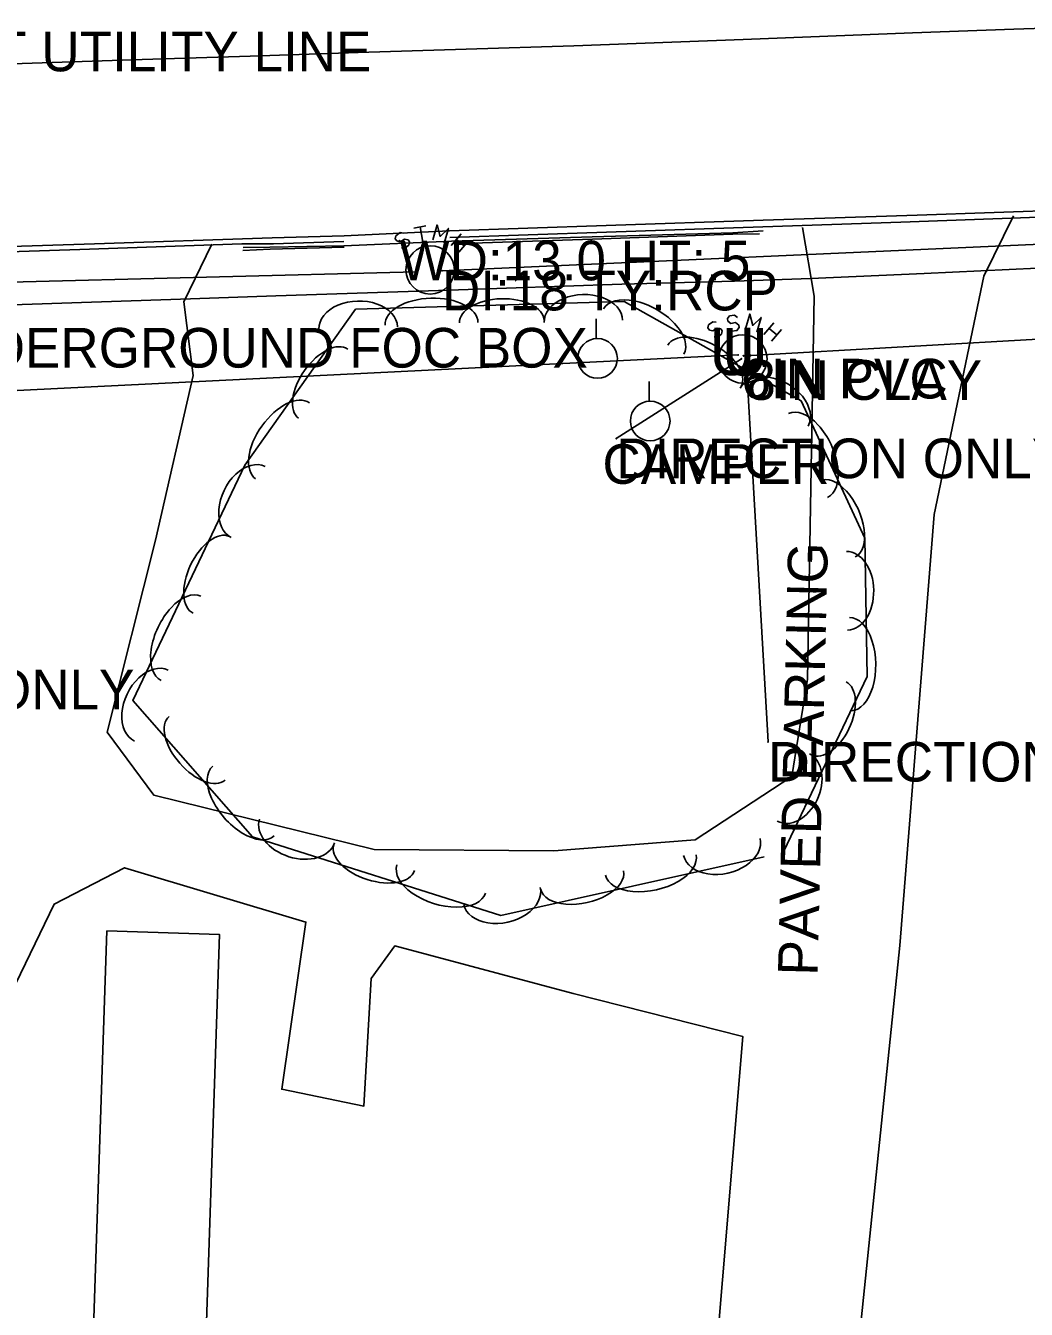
# Model space of a CAD drawing. Extents: x 978516 to 993312, y 1836504 to 1846212.
# Drawn here: x 982988.3 to 983114.4, y 1842518.7 to 1842680.5 of the extents above; entities that cross this region are included whole.
import ezdxf

# ---------------------------------------------------------------- set-up
doc = ezdxf.new("R2010")
doc.units = 0
for name, color, linetype in [('Default', 7, 'Continuous'), ('S_BUILDING', 7, 'Continuous'), ('S_CATCH_BASIN_ANNOT', 7, 'Continuous'), ('S_CURB', 7, 'Continuous'), ('S_DRG_PT_SYM', 7, 'Continuous'), ('S_EDGE_PAVEMENT', 7, 'Continuous'), ('S_ELECTRIC_UTILITIES_ANNOT', 7, 'Continuous'), ('S_MISC_STRUCTURES_ANNOT', 7, 'Continuous'), ('S_PARKING', 7, 'Continuous'), ('S_PARKING_ANNOT', 7, 'Continuous'), ('S_PAVEMENT_CROWN', 7, 'Continuous'), ('S_SANITARY_SEWER', 7, 'Continuous'), ('S_SANITARY_SEWER_ANNOT', 7, 'Continuous'), ('S_SIDEWALK', 7, 'Continuous'), ('S_STORM_SEWER', 7, 'Continuous'), ('S_STORM_SEWER_ANNOT', 7, 'Continuous'), ('S_SURVEY_TEXT_ANNOT', 7, 'Continuous'), ('S_TREE', 7, 'Continuous'), ('S_UNDERGROUND_CABLE', 7, 'Continuous'), ('S_UTILITY_POLE', 7, 'Continuous'), ('S_UTL_PT_SYM', 7, 'Continuous')]:
    doc.layers.add(name, color=color, linetype=linetype)

msp = doc.modelspace()

# ---------------------------------------------------------------- linework, layer by layer
at = {"layer": 'S_BUILDING'}
msp.add_lwpolyline([(982998.5, 1842566.4), (982996.27, 1842500.03), (983010.5, 1842499.55), (983012.72, 1842565.93)], close=True, dxfattribs=at)
at = {"layer": 'S_CURB'}
for points in [[(983041.78, 1842653.78), (983061.51, 1842654.45), (983081.23, 1842655.12), (983098.62, 1842655.72), (983116.01, 1842656.33), (983120.03, 1842656.47), (983141.41, 1842657.25), (983162.79, 1842658.03), (983179.32, 1842658.68), (983195.86, 1842659.33), (983199.41, 1842659.55), (983205.89, 1842659.81)], [(983015.71, 1842652.51), (983019.07, 1842652.56), (983028.41, 1842652.74), (983041.99, 1842653.33), (983059.7, 1842653.85), (983077.42, 1842654.37), (983081.27, 1842654.64)], [(983042.1, 1842652.99), (983059.76, 1842653.58), (983077.42, 1842654.18), (983080.82, 1842654.23)], [(982904.98, 1842649.33), (982922.41, 1842649.89), (982939.84, 1842650.46), (982957.27, 1842651.02), (982974.69, 1842651.59), (982995.11, 1842652.28), (983015.52, 1842652.98), (983019.52, 1842653), (983028.38, 1842653.26)], [(983015.65, 1842652.14), (983019.12, 1842652.31), (983028.44, 1842652.57)]]:
    msp.add_lwpolyline(points, dxfattribs=at)
at = {"layer": 'S_DRG_PT_SYM'}
msp.add_lwpolyline([(983035.43, 1842653.38), (983035.43, 1842653.43), (983035.43, 1842653.38), (983035.38, 1842653.38), (983035.43, 1842653.38), (983035.43, 1842653.33), (983035.43, 1842653.38), (983035.48, 1842653.38)], dxfattribs=at)
at = {"layer": 'S_EDGE_PAVEMENT'}
msp.add_lwpolyline([(982799.93, 1842644.75), (982803.11, 1842645), (982816.92, 1842646.1), (982830.64, 1842646.83), (982844.36, 1842647.55), (982858.08, 1842648.28), (982871.81, 1842649.01), (982891.93, 1842649.67), (982904.86, 1842650.05), (982922.29, 1842650.6), (982939.73, 1842651.16), (982957.17, 1842651.71), (982974.61, 1842652.26), (982996.98, 1842652.99), (983019.36, 1842653.72), (983028.43, 1842653.99), (983041.71, 1842654.6), (983061.49, 1842655.28), (983081.27, 1842655.97), (983100.68, 1842656.61), (983120.09, 1842657.26)], dxfattribs=at)
at = {"layer": 'S_PARKING'}
for points in [[(983077.21, 1842273.31), (983079.69, 1842380.16), (983091.07, 1842492.48), (983098.49, 1842564.53), (983102.83, 1842618.85), (983109.07, 1842648.92), (983112.84, 1842656.52)], [(983086.24, 1842655.06), (983087.68, 1842646.4), (983086.84, 1842598.1), (983084.88, 1842585.84), (983072.67, 1842577.86), (983054.88, 1842576.48), (983032.2, 1842576.64), (983004.43, 1842583.49), (982998.57, 1842591.41), (983004.66, 1842615.62), (983009.41, 1842636.37), (983008.22, 1842645.69), (983011.74, 1842652.92)], [(982984.15, 1842651.53), (982984.99, 1842645.15), (982983.03, 1842614.12), (982974.3, 1842588.15), (982962.33, 1842519.11), (982978.17, 1842519.44), (982985.25, 1842556), (982991.86, 1842569.75), (983000.75, 1842574.33), (983023.62, 1842567.5), (983020.58, 1842546.43), (983030.93, 1842544.29), (983031.86, 1842560.4), (983034.84, 1842564.5), (983057.31, 1842558.5), (983078.68, 1842553.08), (983074.89, 1842507.31), (983067.14, 1842414.68), (983057.78, 1842326.04), (983057.9, 1842278.78)]]:
    msp.add_lwpolyline(points, dxfattribs=at)
at = {"layer": 'S_PAVEMENT_CROWN'}
msp.add_lwpolyline([(982847.58, 1842670.55), (982870.67, 1842671.69), (982893.68, 1842672.48), (982916.68, 1842673.27), (982937.07, 1842674), (982957.45, 1842674.72), (982980.22, 1842675.47), (983002.98, 1842676.22), (983016.59, 1842676.65), (983030.19, 1842677.08), (983043.8, 1842677.51), (983057.4, 1842677.94), (983078.75, 1842678.75), (983100.11, 1842679.56), (983112.88, 1842680.02), (983125.65, 1842680.48)], dxfattribs=at)
at = {"layer": 'S_SANITARY_SEWER'}
for p, q in [((983074.38, 1842642.78), (983074.3, 1842642.39)), ((983074.3, 1842642.39), (983074.5, 1842642.12)), ((983074.92, 1842643.17), (983074.38, 1842642.78)), ((983074.5, 1842642.12), (983074.92, 1842642)), ((983075.35, 1842643.09), (983074.92, 1842643.17)), ((983074.92, 1842642), (983075.47, 1842642.35)), ((983075.47, 1842642.35), (983075.93, 1842642.27)), ((983075.93, 1842642.27), (983076.09, 1842642)), ((983076.09, 1842642), (983076.01, 1842641.58)), ((983081.36, 1842641.54), (983082.6, 1842643.01)), ((983082.01, 1842642.31), (983082.98, 1842641.5)), ((983083.56, 1842642.2), (983082.32, 1842640.72)), ((983075.47, 1842641.19), (983075.08, 1842641.27)), ((983076.01, 1842641.58), (983075.47, 1842641.19)), ((983078.52, 1842638.49), (983062.75, 1842628.44)), ((983079.14, 1842638.31), (983081.88, 1842590.2))]:
    msp.add_line(p, q, dxfattribs=at)
for points in [[(983078.02, 1842643.71), (983077.67, 1842643.98), (983077.02, 1842643.9), (983076.78, 1842643.55), (983076.82, 1842643.24), (983077.17, 1842642.93), (983077.79, 1842643.05), (983078.18, 1842642.74), (983078.22, 1842642.43), (983077.95, 1842642.04), (983077.33, 1842641.96), (983076.98, 1842642.24)], [(983080.46, 1842641.85), (983081.01, 1842643.71), (983079.96, 1842642.7), (983079.57, 1842644.13), (983079.03, 1842642.27)]]:
    msp.add_lwpolyline(points, dxfattribs=at)
msp.add_circle((983078.71, 1842638.47), 3.05, dxfattribs=at)
at = {"layer": 'S_SIDEWALK'}
msp.add_lwpolyline([(982810.26, 1842638.37), (982817.4, 1842638.97), (982827.62, 1842639.18), (982840.18, 1842639.82), (982852.74, 1842640.46), (982865.3, 1842641.1), (982877.86, 1842641.74), (982891.92, 1842642.24), (982905.28, 1842642.67), (982922.7, 1842643.24), (982940.13, 1842643.81), (982957.56, 1842644.38), (982974.98, 1842644.95), (982985.37, 1842645.26), (983009.07, 1842646.03), (983019.82, 1842646.43), (983041.63, 1842647.16), (983063.45, 1842647.9), (983077.67, 1842648.27), (983087.26, 1842648.6), (983101.56, 1842649.26), (983115.86, 1842649.93)], dxfattribs=at)
at = {"layer": 'S_STORM_SEWER'}
for p, q in [((983037.24, 1842654.97), (983038.75, 1842655.24)), ((983038.01, 1842655.12), (983038.36, 1842653.19)), ((983034.95, 1842654), (983034.88, 1842653.61)), ((983034.88, 1842653.61), (983035.07, 1842653.34)), ((983035.5, 1842654.39), (983034.95, 1842654)), ((983035.07, 1842653.34), (983035.5, 1842653.22)), ((983035.92, 1842654.31), (983035.5, 1842654.39)), ((983035.5, 1842653.22), (983036.04, 1842653.57)), ((983036.04, 1842653.57), (983036.5, 1842653.5)), ((983036.5, 1842653.5), (983036.66, 1842653.22)), ((983040.77, 1842649.59), (983148.86, 1842654.38)), ((983041.93, 1842652.76), (983043.17, 1842654.23)), ((983042.59, 1842653.53), (983043.56, 1842652.72)), ((983044.14, 1842653.42), (983042.9, 1842651.95)), ((983036.04, 1842652.41), (983035.65, 1842652.49)), ((983036.58, 1842652.8), (983036.04, 1842652.41)), ((983036.66, 1842653.22), (983036.58, 1842652.8)), ((982904.36, 1842646.08), (983037.51, 1842649.46))]:
    msp.add_line(p, q, dxfattribs=at)
msp.add_lwpolyline([(983041.04, 1842653.07), (983041.58, 1842654.93), (983040.53, 1842653.92), (983040.15, 1842655.36), (983039.6, 1842653.5)], dxfattribs=at)
msp.add_circle((983039.28, 1842649.7), 3.05, dxfattribs=at)
at = {"layer": 'S_TREE'}
msp.add_lwpolyline([(983081.41, 1842575.72), (983048.18, 1842568.31), (983016.88, 1842578.25), (983001.8, 1842595.4), (983015.91, 1842625.07), (983029.87, 1842644.76), (983063.74, 1842645.73), (983086.04, 1842633.21), (983094.09, 1842615.88), (983094.38, 1842598.43), (983083.86, 1842576.44)], dxfattribs=at)
for centre, major_axis, ratio, start_param, end_param in [((983030.21, 1842642.38), (-4.95, -0.15), 0.685874, 3.140501, 6.282094), ((983039.45, 1842642.91), (-5.86, -0.17), 0.550532, 3.140927, 6.282519), ((983048.3, 1842643.17), (-5.34, -0.16), 0.541144, 3.140948, 6.28254), ((983058.6, 1842643.2), (-4.95, -0.15), 0.685874, 3.140501, 6.282094), ((983066.21, 1842641.92), (-5.06, 2.86), 0.554687, 3.145722, 6.287315), ((983073.87, 1842637.61), (-4.61, 2.6), 0.545228, 3.145592, 6.287184), ((983025.79, 1842635.35), (-3.08, -4.36), 0.539235, 3.137057, 6.278649), ((983082.64, 1842632.39), (-4.27, 2.42), 0.691042, 3.14841, 6.290003), ((983020.67, 1842628.14), (-3.38, -4.79), 0.54859, 3.136911, 6.278503), ((983086.92, 1842626.3), (-2.43, 5.3), 0.551823, 3.150215, 6.291808), ((983016.34, 1842620.45), (-2.12, -4.48), 0.68184, 3.138691, 6.280284), ((983090.63, 1842618.32), (-2.21, 4.82), 0.542415, 3.149944, 6.291537), ((983011.68, 1842611.26), (-2.29, -4.83), 0.537963, 3.139869, 6.281461), ((983091.83, 1842609.25), (-0.07, 4.95), 0.68157, 3.144241, 6.285833), ((983007.87, 1842603.26), (-2.51, -5.3), 0.547295, 3.139813, 6.281406), ((983092.25, 1842600), (-0.09, 5.87), 0.547078, 3.143217, 6.28481), ((983004.13, 1842594.78), (-2.12, -4.48), 0.68184, 3.138691, 6.280284), ((983089.53, 1842593.18), (2.12, 4.62), 0.564923, 3.114029, 6.255621), ((983009.89, 1842589.4), (3.53, -4.01), 0.539718, 3.139684, 6.281276), ((983085.07, 1842584.46), (1.89, 4.32), 0.715553, 3.092827, 6.234419), ((983015.75, 1842582.75), (3.88, -4.4), 0.549082, 3.139622, 6.281215), ((983022.49, 1842578.97), (4.72, -1.5), 0.685713, 3.14073, 6.282322), ((983076.06, 1842576.96), (4.83, 1.07), 0.685496, 3.143879, 6.285472), ((983032.22, 1842575.61), (5.09, -1.62), 0.541017, 3.141083, 6.282675), ((983067.09, 1842574.7), (5.72, 1.27), 0.550229, 3.142988, 6.284581), ((983040.67, 1842572.92), (5.59, -1.77), 0.550403, 3.141066, 6.282659), ((983058.44, 1842572.77), (5.21, 1.16), 0.540846, 3.142944, 6.284537), ((983048.34, 1842570.79), (4.83, 1.07), 0.685496, 3.143879, 6.285472)]:
    msp.add_ellipse(centre, major_axis=major_axis, ratio=ratio, start_param=start_param, end_param=end_param, dxfattribs=at)
at = {"layer": 'S_UNDERGROUND_CABLE'}
for p, q in [((983079.69, 1842638.91), (983125.88, 1842641.52)), ((982943.42, 1842632.31), (983078.1, 1842638.97))]:
    msp.add_line(p, q, dxfattribs=at)
at = {"layer": 'S_UTILITY_POLE'}
for p, q in [((983060.23, 1842641.06), (983060.23, 1842643.54)), ((983066.88, 1842633.17), (983066.88, 1842635.65))]:
    msp.add_line(p, q, dxfattribs=at)
for centre in [(983060.38, 1842638.54), (983067.02, 1842630.65)]:
    msp.add_circle(centre, 2.5, dxfattribs=at)
at = {"layer": 'S_UTL_PT_SYM'}
for points in [[(983037.51, 1842649.46), (983037.51, 1842649.51), (983037.51, 1842649.46), (983037.46, 1842649.46), (983037.51, 1842649.46), (983037.51, 1842649.41), (983037.51, 1842649.46), (983037.56, 1842649.46)], [(983039.41, 1842649.84), (983039.41, 1842649.89), (983039.41, 1842649.84), (983039.36, 1842649.84), (983039.41, 1842649.84), (983039.41, 1842649.79), (983039.41, 1842649.84), (983039.46, 1842649.84)], [(983040.77, 1842649.59), (983040.77, 1842649.64), (983040.77, 1842649.59), (983040.72, 1842649.59), (983040.77, 1842649.59), (983040.77, 1842649.54), (983040.77, 1842649.59), (983040.82, 1842649.59)], [(983078.1, 1842638.97), (983078.1, 1842639.02), (983078.1, 1842638.97), (983078.05, 1842638.97), (983078.1, 1842638.97), (983078.1, 1842638.92), (983078.1, 1842638.97), (983078.15, 1842638.97)], [(983078.79, 1842638.87), (983078.79, 1842638.92), (983078.79, 1842638.87), (983078.74, 1842638.87), (983078.79, 1842638.87), (983078.79, 1842638.82), (983078.79, 1842638.87), (983078.84, 1842638.87)], [(983079.69, 1842638.91), (983079.69, 1842638.96), (983079.69, 1842638.91), (983079.64, 1842638.91), (983079.69, 1842638.91), (983079.69, 1842638.86), (983079.69, 1842638.91), (983079.74, 1842638.91)], [(983078.52, 1842638.49), (983078.52, 1842638.54), (983078.52, 1842638.49), (983078.47, 1842638.49), (983078.52, 1842638.49), (983078.52, 1842638.44), (983078.52, 1842638.49), (983078.57, 1842638.49)], [(983079.14, 1842638.31), (983079.14, 1842638.36), (983079.14, 1842638.31), (983079.09, 1842638.31), (983079.14, 1842638.31), (983079.14, 1842638.26), (983079.14, 1842638.31), (983079.19, 1842638.31)], [(983062.75, 1842628.44), (983062.75, 1842628.49), (983062.75, 1842628.44), (983062.7, 1842628.44), (983062.75, 1842628.44), (983062.75, 1842628.39), (983062.75, 1842628.44), (983062.8, 1842628.44)], [(983081.88, 1842590.2), (983081.88, 1842590.25), (983081.88, 1842590.2), (983081.83, 1842590.2), (983081.88, 1842590.2), (983081.88, 1842590.15), (983081.88, 1842590.2), (983081.93, 1842590.2)]]:
    msp.add_lwpolyline(points, dxfattribs=at)

# ---------------------------------------------------------------- texts
at = {"layer": 'Default'}
for p in [(983074.47, 1842636.43), (983076.06, 1842636.36)]:
    msp.add_text('U', height=6, dxfattribs=at).set_placement(p)
at = {"layer": 'S_CATCH_BASIN_ANNOT'}
msp.add_text('WD:13.0 HT:.5', height=5, dxfattribs=at).set_placement((983035.43, 1842648.38))
at = {"layer": 'S_ELECTRIC_UTILITIES_ANNOT'}
msp.add_text('LOWEST UTILITY LINE', height=5, dxfattribs=at).set_placement((982960.17, 1842674.73))
at = {"layer": 'S_MISC_STRUCTURES_ANNOT'}
msp.add_text('UNDERGROUND FOC BOX', height=5, dxfattribs=at).set_placement((982973.72, 1842637.38))
at = {"layer": 'S_PARKING_ANNOT'}
msp.add_text('PAVED PARKING', height=5.0005, rotation=88.6282, dxfattribs=at).set_placement((983088.12, 1842560.69))
at = {"layer": 'S_SANITARY_SEWER_ANNOT'}
for s, p in [('6IN PVC', (983078.52, 1842633.49)), ('8IN CLAY', (983079.14, 1842633.31)), ('DIRECTION ONLY DEPTH UNKNON', (983062.75, 1842623.44)), ('DIRECTION ONLY', (982945.15, 1842594.29)), ('DIRECTION ONLY', (983081.88, 1842585.2))]:
    msp.add_text(s, height=5, dxfattribs=at).set_placement(p)
at = {"layer": 'S_STORM_SEWER_ANNOT'}
msp.add_text('DI:18 TY:RCP', height=5, dxfattribs=at).set_placement((983040.77, 1842644.59))
at = {"layer": 'S_SURVEY_TEXT_ANNOT'}
msp.add_text('CAMPER', height=5, dxfattribs=at).set_placement((983061, 1842622.73))

doc.saveas('drawing.dxf')
